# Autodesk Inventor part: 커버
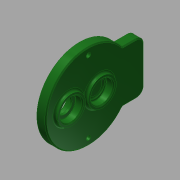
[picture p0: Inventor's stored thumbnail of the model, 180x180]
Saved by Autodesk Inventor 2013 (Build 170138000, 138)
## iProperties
Created: 2016-02
Part Number: 커버
Material: 일반
Document SubType Name: Modeling
Designer: mduedu
Density: 1 g/cm^3
Mass: 58.0254 g
Surface Area: 178.476 cm^2
Volume: 58.0254 cm^3
Author: mduedu
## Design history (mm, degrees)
sketch "스케치1"
  geometry: C1 r 43 at (0, 0); 1 further point
  constraints: 1 centre point, 1 coincident
  dimensions: "d0" = 86 diameter of C1
extrude "돌출1" new body sketch "스케치1" distance "d1" = 9; taper "d2" = 0 deg
sketch "스케치2"
  geometry: C1 r 14 at (0, 11); 1 further point
  constraints: 1 centre point, 1 vertical alignment
  dimensions: "d3" = 28 diameter of C1; "d6" = 11 distance of C1.centre point (0, 0)
extrude "돌출2" join sketch "스케치2" distance "d7" = 3; taper "d8" = 0 deg
sketch "스케치3"
  geometry: C1 r 14 at (0, -20); 1 further point
  constraints: 1 centre point, 1 vertical alignment
  dimensions: "d9" = 28 diameter of C1; "d10" = 20 distance of C1.centre point (0, 0)
extrude "돌출3" join sketch "스케치3" distance "d11" = 3; taper "d12" = 0 deg
hole "구멍1" diameter "d15" = 22; stored, may be unused: countersink angle "d19" = 90 deg, drill point angle "d21" = 0 deg; dims "d13" = 10, "d14" = 10, "d16" = 6, "d17" = 4, "d18" = 2, "d20" = 7
hole "구멍2" diameter "d24" = 18; stored, may be unused: countersink angle "d28" = 90 deg, drill point angle "d30" = 0 deg; dims "d22" = 10, "d23" = 10, "d25" = 6, "d26" = 4, "d27" = 2, "d29" = 1
hole "구멍3" diameter "d33" = 22; stored, may be unused: countersink angle "d37" = 90 deg, drill point angle "d39" = 0 deg; dims "d34" = 6, "d35" = 4, "d36" = 2, "d38" = 7, "d73" = 10, "d74" = 10
sketch "스케치7"
  geometry: L1 (-26, 34.249)-(26, 34.249); L2 (26, 34.249)-(26, 56); L3 (26, 56)-(-26, 56); L4 (-26, 56)-(-26, 34.249); A1 r 43 centre (0, 0) between (-26, 34.249) and (26, 34.249) reference; 1 further point
  constraints: 8 end point, 2 parallel, 2 point on circle, 1 horizontal, 1 perpendicular
  dimensions: "d95" = 52 distance of L2.end L3.end; "d97" = 56 distance from line of L3 point (0, 0)
extrude "돌출5" join sketch "스케치7" stored distance "d98" = 10; taper "d99" = 0 deg
sketch "스케치4"
  geometry: C1 r 14 at (0, -20) reference; C2 r 18 at (0, -20); 1 further point
  constraints: 1 centre point, 1 coincident
  dimensions: "d40" = 36 diameter of C2
extrude "돌출4" join sketch "스케치4" distance "d41" = 4; taper "d42" = 0 deg
hole "구멍4" diameter "d45" = 22; stored, may be unused: countersink angle "d49" = 90 deg, drill point angle "d51" = 0 deg; dims "d43" = 10, "d44" = 10, "d46" = 6, "d47" = 4, "d48" = 2, "d50" = 7
hole "구멍5" diameter "d54" = 15; stored, may be unused: countersink angle "d58" = 90 deg, drill point angle "d60" = 0 deg; dims "d52" = 10, "d53" = 10, "d55" = 6, "d56" = 4, "d57" = 2, "d59" = 7
fillet "모깎기1" dims "d61" = 0.3
fillet "모깎기2" dims "d62" = 2
chamfer "모따기1" distance "d63" = 1; stored, may be unused: second distance "d64" = 2, angle "d65" = 45 deg
fillet "모깎기6" dims "d88" = 2
sketch "스케치5" dims "d67" = 72
  geometry: 4 further points
  constraints: 2 horizontal alignment, 1 coincident, 5 other
  dimensions: "d71" = 360 deg dimension on point (0, 0) point (-36, 0) (derived)
fillet "모깎기4" dims "d75" = 2
sketch "스케치6"
  geometry: 2 further points
hole "구멍6" sketch "스케치6" at (36, 0), (-36, 0) diameter "d76" = 4.5; stored, may be unused: countersink angle "d80" = 90 deg, drill point angle "d82" = 0 deg; dims "d77" = 6, "d78" = 8, "d79" = 4.6, "d81" = 8
fillet "모깎기7" dims "d100" = 8, "d101" = 2
chamfer "모따기2" distance "d90" = 1; stored, may be unused: second distance "d91" = 2, angle "d92" = 45 deg
node "솔리드1"
node "절단 모서리 투영1"
